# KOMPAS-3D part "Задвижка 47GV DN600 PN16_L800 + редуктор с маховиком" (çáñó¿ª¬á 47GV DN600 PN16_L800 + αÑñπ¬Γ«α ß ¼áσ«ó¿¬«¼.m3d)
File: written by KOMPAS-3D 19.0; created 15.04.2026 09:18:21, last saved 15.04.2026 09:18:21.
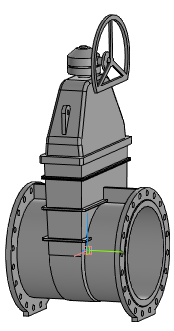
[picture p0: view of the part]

Document properties: Автор: Энергия; Полное имя файла: ..\..\Задвижка 47GV DN600 PN16_L800 + редуктор с маховиком.a3d

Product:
- Part/product: Задвижка 47GV DN600 PN16_L800 + редуктор с маховиком
    Масса: 1678.71

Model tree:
1. Операция без истории:1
